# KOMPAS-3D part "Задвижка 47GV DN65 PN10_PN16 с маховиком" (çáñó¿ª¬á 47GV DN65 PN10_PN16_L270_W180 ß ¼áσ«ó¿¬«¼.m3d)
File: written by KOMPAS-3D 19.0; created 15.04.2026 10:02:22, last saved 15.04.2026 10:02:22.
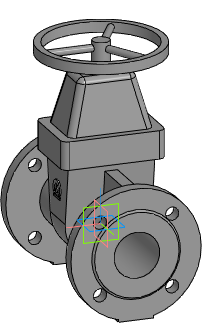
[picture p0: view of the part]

Document properties: Автор: Евгений; Полное имя файла: Z:\3.Личные\kachalov\3d для проектировщиков\2.1 Тип 47GV, 47GV.Z\Задвижка 47GV_DN40-DN600\stp_Задвижка 47GV\Задвижка 47GV DN65 PN10_PN16_L270_W180 с маховиком.m3d

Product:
- Part/product: Задвижка 47GV DN65 PN10_PN16 с маховиком

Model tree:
1. Операция без истории:1  (labels: Задвижка 47GV DN65 PN10_PN16 с маховиком)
